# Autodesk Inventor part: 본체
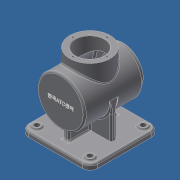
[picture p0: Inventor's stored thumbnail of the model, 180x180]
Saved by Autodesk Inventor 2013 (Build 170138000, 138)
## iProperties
Created: 2015-07
Part Number: 본체
Material: 일반
Document SubType Name: Modeling
Designer: Administrator
Density: 1 g/cm^3
Author: Administrator
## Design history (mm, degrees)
sketch "스케치1"
  geometry: L1 (-65, 65)-(65, 65); L2 (65, 65)-(65, -65); L3 (65, -65)-(-65, -65); L4 (-65, -65)-(-65, 65); 3 further points
  constraints: 8 end point, 2 midpoint, 2 parallel, 1 horizontal, 1 horizontal alignment, 1 perpendicular, 1 vertical alignment
  dimensions: "d0" = 130 distance of L1.start L1.end; "d2" = 130 distance of L1.end L2.end
extrude "돌출1" new body sketch "스케치1" distance "d3" = 10; taper "d4" = 0 deg
node "작업 평면1"
node "작업 평면2"
node "작업 평면3"
sketch "스케치8"
  geometry: L1 (0, 0)-(130, 0) reference; L2 (130, 0)-(130, -10) reference; L3 (0, -10)-(130, -10) reference; L4 (0, 0)-(0, -10) reference; C1 r 45 at (65, 68); 2 further points
  constraints: 1 centre point, 1 midpoint, 1 vertical alignment
  dimensions: "d32" = 90 diameter of C1; "d34" = 78 distance from line of L3 C1.centre
extrude "돌출7" join sketch "스케치8" distance "d35" = 110; taper "d36" = 0 deg
sketch "스케치5"
  geometry: L1 (-45, 5)-(45, 5); L2 (45, 5)-(45, -5); L3 (45, -5)-(-45, -5); L4 (-45, -5)-(-45, 5); L5 (-5, 45)-(5, 45); L6 (5, 45)-(5, -45); L7 (5, -45)-(-5, -45); L8 (-5, -45)-(-5, 45); 5 further points
  constraints: 16 end point, 4 midpoint, 4 parallel, 2 horizontal, 2 horizontal alignment, 2 perpendicular, 2 vertical alignment
  dimensions: "d19" = 10 distance of L1.end L2.end; "d21" = 90 distance of L2.end L3.end; "d27" = 10 distance of L6.end L7.end; "d28" = 90 distance of L7.end L5.start
extrude "돌출6" join sketch "스케치5" stored distance "d29" = 7; taper "d30" = 0 deg
sketch "스케치9"
  geometry: C1 r 45 at (0, 0) reference; C2 r 38 at (0, 0); 1 further point
  constraints: 1 centre point, 1 coincident
  dimensions: "d37" = 76 diameter of C2
extrude "돌출8" join sketch "스케치9" distance "d40" = 7; taper "d41" = 0 deg
node "작업 평면4"
sketch "스케치10"
  geometry: L1 (45, 55)-(-45, 55) reference; L2 (45, -55)-(-45, -55) reference; L3 (45, -5)-(45, 5) reference; L4 (45, -5)-(5, -5) reference; L5 (5, -5)-(5, -45) reference; L6 (5, -45)-(-5, -45) reference; L7 (-5, -45)-(-5, -5) reference; L8 (-5, -5)-(-45, -5) reference; L9 (-45, -5)-(-45, 5) reference; L10 (-45, 5)-(-5, 5) reference; L11 (-5, 5)-(-5, 45) reference; L12 (-5, 45)-(5, 45) reference; L13 (5, 45)-(5, 5) reference; L14 (5, 5)-(45, 5) reference; L15 (45, 5)-(5, 5) reference; L16 (5, 5)-(5, 45) reference; L17 (5, 45)-(-5, 45) reference; L18 (-5, 45)-(-5, 5) reference; L19 (-5, 5)-(-45, 5) reference; L20 (-45, 5)-(-45, -5) reference; L21 (-45, -5)-(-5, -5) reference; L22 (-5, -5)-(-5, -45) reference; L23 (-5, -45)-(5, -45) reference; L24 (5, -45)-(5, -5) reference; L25 (5, -5)-(45, -5) reference; L26 (45, -5)-(45, 5) reference; L27 (65, 65)-(-65, 65) reference; L28 (65, -65)-(65, 65) reference; L29 (-65, -65)-(65, -65) reference; L30 (-65, 65)-(-65, -65) reference; C1 r 38 at (0, 0); 1 further point
  constraints: 1 centre point, 1 coincident
  dimensions: "d43" = 76 diameter of C1
extrude "돌출9" join sketch "스케치10" stored distance "d45" = 7; taper "d46" = 0 deg
sketch "스케치12"
  geometry: L1 (62, 30)-(55, 30) reference; L2 (55, 30)-(55, 23) reference; L3 (55, 23)-(45, 23) reference; L4 (45, 23)-(45, 0) reference; L5 (45, 0)-(65, 0) reference; L6 (65, 0)-(65, -10) reference; L7 (65, -10)-(-65, -10) reference; L8 (-65, -10)-(-65, 0) reference; L9 (-65, 0)-(-45, 0) reference; L10 (-45, 0)-(-45, 23) reference; L11 (-45, 23)-(-55, 23) reference; L12 (-55, 23)-(-55, 113) reference; L13 (-55, 113)-(-38, 113) reference; L14 (-38, 113)-(-38, 130) reference; L15 (-38, 130)-(38, 130) reference; L16 (38, 130)-(38, 113) reference; L17 (38, 113)-(55, 113) reference; L18 (55, 113)-(55, 106) reference; L19 (55, 106)-(62, 106) reference; L20 (62, 106)-(62, 30) reference; L21 (62, 68)-(-55, 68); L22 (62, 95)-(48, 95); L23 (48, 95)-(48, 108); L24 (48, 108)-(-48, 108); L25 (-48, 108)-(-48, 68); 1 further point
  constraints: 10 end point, 2 midpoint, 2 parallel, 2 perpendicular, 2 point on line
  dimensions: "d49" = 80 diameter of L24 L21; "d51" = 14 distance between parallel lines of L20 L23; "d52" = 54 diameter of L22 L21; "d112" = 96 distance between parallel lines of L25 L23
revolve "회전1" sketch "스케치12" stored, may be unused: angle "d54" = 90 deg
hole "구멍1" diameter "d57" = 54; stored, may be unused: countersink angle "d61" = 90 deg, drill point angle "d63" = 118 deg; dims "d55" = 10, "d56" = 10, "d58" = 6, "d59" = 4, "d60" = 2, "d62" = 8
sketch "스케치13"
  geometry: C1 r 27 at (0, 0) reference; C2 r 38 at (0, 0) reference; 2 further points
  constraints: 1 vertical alignment
  dimensions: "d64" = 32 distance of point (0, 32) point (0, 0)
hole "구멍2" sketch "스케치13" at (0, 32) diameter "d65" = 3.242; stored, may be unused: countersink angle "d69" = 90 deg, drill point angle "d71" = 118 deg; dims "d66" = 8, "d67" = 4, "d68" = 2, "d70" = 10
sketch "스케치14"
  geometry: C1 r 27 at (0, 0) reference; C2 r 38 at (0, 0) reference; 2 further points
  constraints: 1 vertical alignment
  dimensions: "d75" = 32 distance of point (0, 32) C1.centre
hole "구멍3" sketch "스케치14" at (0, 32) diameter "d76" = 3.242; stored, may be unused: countersink angle "d80" = 90 deg, drill point angle "d82" = 118 deg; dims "d77" = 8, "d78" = 4, "d79" = 2, "d81" = 10
sketch "스케치15"
  geometry: L1 (-65, 65)-(65, 65) reference; L2 (-65, -65)-(-65, 65) reference; L3 (65, -65)-(-65, -65) reference; L4 (65, 65)-(65, -65) reference; L5 (5, 45)-(5, 5) reference; L6 (5, 5)-(45, 5) reference; L7 (45, 5)-(45, -5) reference; L8 (45, -5)-(5, -5) reference; L9 (5, -5)-(5, -45) reference; L10 (5, -45)-(-5, -45) reference; L11 (-5, -45)-(-5, -5) reference; L12 (-5, -5)-(-45, -5) reference; L13 (-45, -5)-(-45, 5) reference; L14 (-45, 5)-(-5, 5) reference; L15 (-5, 5)-(-5, 45) reference; L16 (-5, 45)-(5, 45) reference; C1 r 7.5 at (-50, -50); C2 r 27 at (0, 0) reference; C3 r 1.621 at (32, 0) reference; C4 r 1.621 at (0, -32) reference; C5 r 1.621 at (-32, 0) reference; C6 r 1.621 at (0, 32) reference; C7 r 27 at (0, 0) reference; C8 r 38 at (0, 0) reference; 1 further point
  constraints: 1 centre point
  dimensions: "d86" = 50 horizontal distance of point (0, 0) C1.centre; "d87" = 15 diameter of C1; "d111" = 50 horizontal distance of point (0, 0) C1.centre
extrude "돌출10" join sketch "스케치15" distance "d88" = 3; taper "d89" = 0 deg
hole "구멍4" diameter "d92" = 10; stored, may be unused: countersink angle "d96" = 90 deg, drill point angle "d98" = 0 deg; dims "d90" = 10, "d91" = 10, "d93" = 8, "d94" = 4, "d95" = 2, "d97" = 10
sketch "스케치16"
  geometry: C1 r 45 at (0, 0) reference; 2 further points
  constraints: 1 coincident, 1 other
feature "엠보싱1" sketch "스케치16" dims "d0" = 130, "d2" = 130, "d19" = 10, "d21" = 90, "d27" = 10, "d28" = 90, "d99" = 0.5, "d100" = 0
chamfer "모따기1" distance "d101" = 1; stored, may be unused: second distance "d102" = 2, angle "d103" = 45 deg
fillet "모깎기1" dims "d104" = 15
fillet "모깎기2" dims "d105" = 3
fillet "모깎기3" dims "d106" = 3
fillet "모깎기4" dims "d107" = 3
fillet "모깎기5" dims "d108" = 3
fillet "모깎기6" dims "d109" = 3
fillet "모깎기7" dims "d110" = 3
node "솔리드1"
pattern_circular "원형 패턴1" dims angle "d73" = 360 deg
pattern_circular "원형 패턴2" dims angle "d84" = 360 deg
mirror "대칭1"
mirror "대칭2"
node "투영된 루프5"
node "투영된 루프6"
node "투영된 루프7"
node "투영된 루프8"
node "투영된 루프10"
node "투영된 루프11"
node "투영된 루프12"
node "투영된 루프13"
node "투영된 루프14"
node "절단 모서리 투영1"
